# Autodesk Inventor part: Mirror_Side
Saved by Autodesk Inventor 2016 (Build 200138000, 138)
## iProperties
Created: 2015-11
Part Number: Mirror_Side
Material: Generic
Document SubType Name: Modeling
Designer: John
Density: 1 g/cm^3
Appearance: Default
Author: John
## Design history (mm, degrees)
feature "SOLID1"
body "Solid1"
